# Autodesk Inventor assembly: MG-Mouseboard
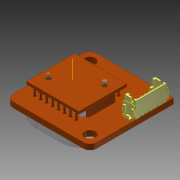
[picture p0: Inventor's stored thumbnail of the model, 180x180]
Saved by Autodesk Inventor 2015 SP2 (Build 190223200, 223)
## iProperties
Created: 2015-10
Part Number: MG-Mouseboard
Document SubType Name: Assembly
Designer: rYan
Author: rYan
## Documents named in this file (6)
- E:\Tigers SVN\mechanik\2016\Inventor\Elektronik\MG-Mouseboard.iam
- E:\Tigers SVN\mechanik\2016\Inventor\Elektronik\Mouseboard.ipt
- E:\Tigers SVN\mechanik\2016\Inventor\Kaufteile\ADNS9800.ipt
- E:\Tigers SVN\mechanik\2016\Inventor\Kaufteile\ADNS-6190-002.ipt
- E:\Tigers SVN\mechanik\2016\Inventor\Kaufteile\DF13C-6P-1.25V.ipt
- DF13C-6P-1.25V.ipt
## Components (4 placed, 4 different names)
1. Mouseboard:1 — Passend:1, Passend:2, Passend:3, Fluchtend:1, Passend:6, Fluchtend:2, Fluchtend:3
2. ADNS9800:1 — Passend:1, Passend:2, Passend:3, Passend:4, Passend:5
3. ADNS-6190-002:1 — Passend:4, Passend:5, Fluchtend:1
4. DF13C-6P-1.25V:1 — Passend:6, Fluchtend:2, Fluchtend:3
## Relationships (9: Mate 6, Flush 3)
- Passend:1 [Mate]: Mouseboard:1 ↔ ADNS9800:1
- Passend:2 [Mate]: Mouseboard:1 ↔ ADNS9800:1
- Passend:3 [Mate]: Mouseboard:1 ↔ ADNS9800:1
- Passend:4 [Mate]: ADNS9800:1 ↔ ADNS-6190-002:1
- Passend:5 [Mate]: ADNS9800:1 ↔ ADNS-6190-002:1
- Fluchtend:1 [Flush]: Mouseboard:1 ↔ ADNS-6190-002:1
- Passend:6 [Mate]: Mouseboard:1 ↔ DF13C-6P-1.25V:1
- Fluchtend:2 [Flush]: Mouseboard:1 ↔ DF13C-6P-1.25V:1
- Fluchtend:3 [Flush]: Mouseboard:1 ↔ DF13C-6P-1.25V:1
